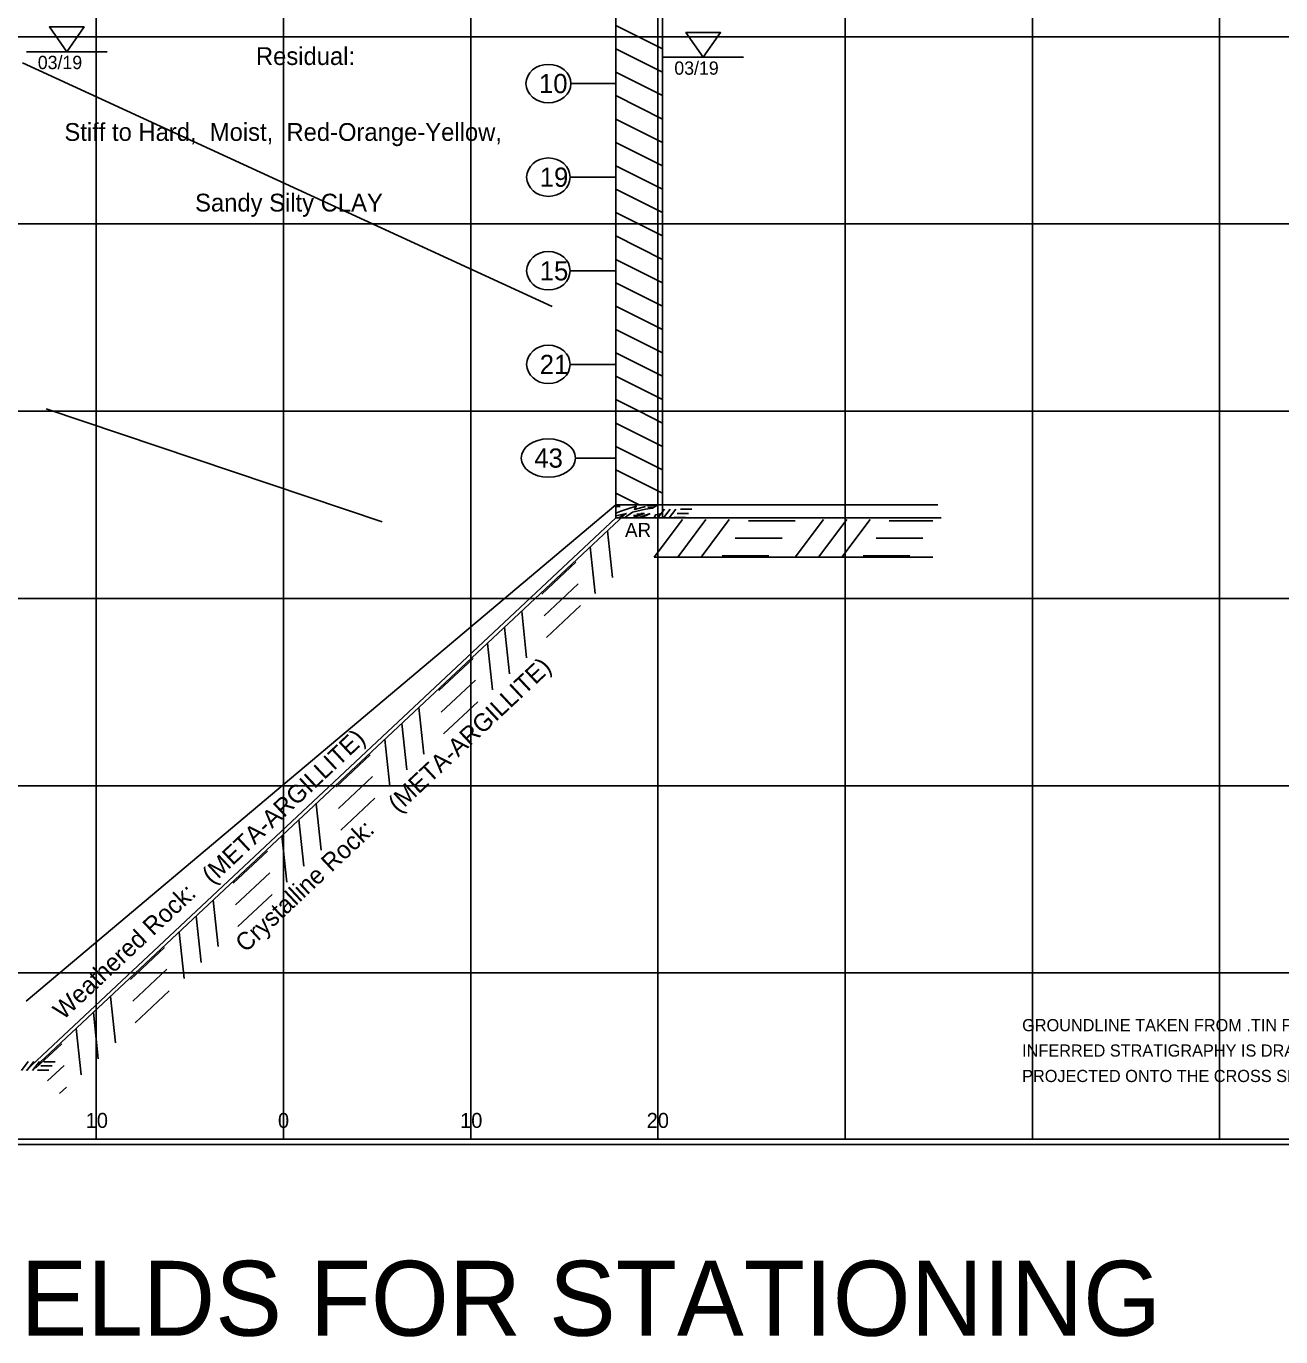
# Model space of a CAD drawing. Extents: x 278618 to 280654, y 171155 to 171855.
# Drawn here: x 280080.4 to 280147.4, y 171178.3 to 171248.3 of the extents above; entities that cross this region are included whole.
import ezdxf

# ---------------------------------------------------------------- set-up
doc = ezdxf.new("R2010")
doc.units = 0
for name, color, linetype in [('Exist Vertical Profile Ground Line', 7, 'Continuous'), ('Geotech Sheets and Borders Cell', 7, 'Continuous'), ('Prop Road Sect_ Boring - Material (Outline)', 7, 'Continuous'), ('Prop Road Sect_ Boring - Peripheral (HR Indicator)', 7, 'Continuous'), ('Prop Road Sect_ Boring - Peripheral (SPT Oval + Leader)', 7, 'Continuous'), ('Prop Road Sect_ Boring - Peripheral (SPT Tx)', 7, 'Continuous'), ('Prop Road Sect_ Material - Contact (General - Major)', 7, 'Continuous'), ('Prop Road Sect_ Material - Tx (Composite Desc)', 7, 'Continuous'), ('Prop Strc Sect_ Grid - minor', 7, 'Continuous'), ('Prop Strc Sect_ Material - Contact (General - Major)', 7, 'Continuous'), ('Scratch_Level_4', 7, 'Continuous'), ('Sheet Plot Border Inside CELL', 7, 'Continuous'), ('Water Mark (0 Hr) Cell', 7, 'Continuous'), ('Water Mark (24 Hr) Cell', 7, 'Continuous'), ('Water Mark (Dry) Cell', 7, 'Continuous')]:
    doc.layers.add(name, color=color, linetype=linetype)

msp = doc.modelspace()

# ---------------------------------------------------------------- linework, layer by layer
at = {"layer": 'Geotech Sheets and Borders Cell'}
msp.add_lwpolyline([(280024.125, 171293.859), (280174.125, 171293.859), (280174.125, 171188.859), (280024.125, 171188.859)], close=True, dxfattribs=at)
at = {"layer": 'Prop Road Sect_ Boring - Material (Outline)'}
for p, q in [((280111.875, 171248.342), (280113.123, 171247.718)), ((280111.875, 171248.342), (280113.123, 171247.718)), ((280113.123, 171247.718), (280114.372, 171247.094)), ((280113.123, 171247.718), (280114.372, 171247.094)), ((280111.875, 171247.094), (280114.372, 171245.845)), ((280111.875, 171247.094), (280114.372, 171245.845)), ((280111.875, 171247.094), (280114.372, 171245.845)), ((280111.875, 171247.094), (280114.372, 171245.845)), ((280114.372, 171247.094), (280114.375, 171247.092)), ((280114.372, 171247.094), (280114.375, 171247.092)), ((280114.372, 171247.094), (280114.375, 171247.092)), ((280114.372, 171247.094), (280114.375, 171247.092)), ((280111.875, 171245.845), (280113.123, 171245.22)), ((280111.875, 171245.845), (280113.123, 171245.22)), ((280114.372, 171245.845), (280114.375, 171245.844)), ((280114.372, 171245.845), (280114.375, 171245.844)), ((280113.123, 171245.22), (280114.372, 171244.596)), ((280113.123, 171245.22), (280114.372, 171244.596)), ((280111.875, 171244.596), (280114.372, 171243.347)), ((280111.875, 171244.596), (280114.372, 171243.347)), ((280111.875, 171244.596), (280114.372, 171243.347)), ((280111.875, 171244.596), (280114.372, 171243.347)), ((280114.372, 171244.596), (280114.375, 171244.595)), ((280114.372, 171244.596), (280114.375, 171244.595)), ((280114.372, 171244.596), (280114.375, 171244.595)), ((280114.372, 171244.596), (280114.375, 171244.595)), ((280111.875, 171243.347), (280113.123, 171242.723)), ((280111.875, 171243.347), (280113.123, 171242.723)), ((280114.372, 171243.347), (280114.375, 171243.346)), ((280114.372, 171243.347), (280114.375, 171243.346)), ((280113.123, 171242.723), (280114.372, 171242.099)), ((280113.123, 171242.723), (280114.372, 171242.099)), ((280111.875, 171242.099), (280114.372, 171240.85)), ((280111.875, 171242.099), (280114.372, 171240.85)), ((280111.875, 171242.099), (280114.372, 171240.85)), ((280111.875, 171242.099), (280114.372, 171240.85)), ((280114.372, 171242.099), (280114.375, 171242.097)), ((280114.372, 171242.099), (280114.375, 171242.097)), ((280114.372, 171242.099), (280114.375, 171242.097)), ((280114.372, 171242.099), (280114.375, 171242.097)), ((280111.875, 171240.85), (280113.123, 171240.225)), ((280111.875, 171240.85), (280113.123, 171240.225)), ((280114.372, 171240.85), (280114.375, 171240.849)), ((280114.372, 171240.85), (280114.375, 171240.849)), ((280113.123, 171240.225), (280114.372, 171239.601)), ((280113.123, 171240.225), (280114.372, 171239.601)), ((280111.875, 171239.601), (280114.372, 171238.352)), ((280111.875, 171239.601), (280114.372, 171238.352)), ((280111.875, 171239.601), (280114.372, 171238.352)), ((280111.875, 171239.601), (280114.372, 171238.352)), ((280114.372, 171239.601), (280114.375, 171239.6)), ((280114.372, 171239.601), (280114.375, 171239.6)), ((280114.372, 171239.601), (280114.375, 171239.6)), ((280114.372, 171239.601), (280114.375, 171239.6)), ((280111.875, 171238.352), (280113.123, 171237.728)), ((280111.875, 171238.352), (280113.123, 171237.728)), ((280114.372, 171238.352), (280114.375, 171238.351)), ((280114.372, 171238.352), (280114.375, 171238.351)), ((280113.123, 171237.728), (280114.372, 171237.103)), ((280113.123, 171237.728), (280114.372, 171237.103)), ((280111.875, 171237.103), (280114.372, 171235.855)), ((280111.875, 171237.103), (280114.372, 171235.855)), ((280111.875, 171237.103), (280114.372, 171235.855)), ((280111.875, 171237.103), (280114.372, 171235.855)), ((280114.372, 171237.103), (280114.375, 171237.102)), ((280114.372, 171237.103), (280114.375, 171237.102)), ((280114.372, 171237.103), (280114.375, 171237.102)), ((280114.372, 171237.103), (280114.375, 171237.102)), ((280111.875, 171235.855), (280113.123, 171235.23)), ((280111.875, 171235.855), (280113.123, 171235.23)), ((280114.372, 171235.855), (280114.375, 171235.853)), ((280114.372, 171235.855), (280114.375, 171235.853)), ((280113.123, 171235.23), (280114.372, 171234.606)), ((280113.123, 171235.23), (280114.372, 171234.606)), ((280111.875, 171234.606), (280114.372, 171233.357)), ((280111.875, 171234.606), (280114.372, 171233.357)), ((280111.875, 171234.606), (280114.372, 171233.357)), ((280111.875, 171234.606), (280114.372, 171233.357)), ((280114.372, 171234.606), (280114.375, 171234.605)), ((280114.372, 171234.606), (280114.375, 171234.605)), ((280114.372, 171234.606), (280114.375, 171234.605)), ((280114.372, 171234.606), (280114.375, 171234.605)), ((280111.875, 171233.357), (280113.123, 171232.733)), ((280111.875, 171233.357), (280113.123, 171232.733)), ((280114.372, 171233.357), (280114.375, 171233.356)), ((280114.372, 171233.357), (280114.375, 171233.356)), ((280113.123, 171232.733), (280114.372, 171232.108)), ((280113.123, 171232.733), (280114.372, 171232.108)), ((280111.875, 171232.108), (280114.372, 171230.86)), ((280111.875, 171232.108), (280114.372, 171230.86)), ((280111.875, 171232.108), (280114.372, 171230.86)), ((280111.875, 171232.108), (280114.372, 171230.86)), ((280114.372, 171232.108), (280114.375, 171232.107)), ((280114.372, 171232.108), (280114.375, 171232.107)), ((280114.372, 171232.108), (280114.375, 171232.107)), ((280114.372, 171232.108), (280114.375, 171232.107)), ((280111.875, 171230.86), (280113.123, 171230.235)), ((280111.875, 171230.86), (280113.123, 171230.235)), ((280113.123, 171230.235), (280114.372, 171229.611)), ((280113.123, 171230.235), (280114.372, 171229.611)), ((280114.372, 171230.86), (280114.375, 171230.858)), ((280114.372, 171230.86), (280114.375, 171230.858)), ((280111.875, 171229.611), (280114.372, 171228.362)), ((280111.875, 171229.611), (280114.372, 171228.362)), ((280111.875, 171229.611), (280114.372, 171228.362)), ((280111.875, 171229.611), (280114.372, 171228.362)), ((280114.372, 171229.611), (280114.375, 171229.61)), ((280114.372, 171229.611), (280114.375, 171229.61)), ((280114.372, 171229.611), (280114.375, 171229.61)), ((280114.372, 171229.611), (280114.375, 171229.61)), ((280111.875, 171228.362), (280113.123, 171227.738)), ((280111.875, 171228.362), (280113.123, 171227.738)), ((280114.372, 171228.362), (280114.375, 171228.361)), ((280114.372, 171228.362), (280114.375, 171228.361)), ((280113.123, 171227.738), (280114.372, 171227.113)), ((280113.123, 171227.738), (280114.372, 171227.113)), ((280111.875, 171227.113), (280114.372, 171225.865)), ((280111.875, 171227.113), (280114.372, 171225.865)), ((280111.875, 171227.113), (280114.372, 171225.865)), ((280111.875, 171227.113), (280114.372, 171225.865)), ((280114.372, 171227.113), (280114.375, 171227.112)), ((280114.372, 171227.113), (280114.375, 171227.112)), ((280114.372, 171227.113), (280114.375, 171227.112)), ((280114.372, 171227.113), (280114.375, 171227.112)), ((280111.875, 171225.865), (280113.123, 171225.24)), ((280111.875, 171225.865), (280113.123, 171225.24)), ((280114.372, 171225.865), (280114.375, 171225.863)), ((280114.372, 171225.865), (280114.375, 171225.863)), ((280111.875, 171224.616), (280114.372, 171223.367)), ((280111.875, 171224.616), (280114.372, 171223.367)), ((280111.875, 171224.616), (280114.372, 171223.367)), ((280111.875, 171224.616), (280114.372, 171223.367)), ((280113.123, 171225.24), (280114.372, 171224.616)), ((280113.123, 171225.24), (280114.372, 171224.616)), ((280114.372, 171224.616), (280114.375, 171224.615)), ((280114.372, 171224.616), (280114.375, 171224.615)), ((280114.372, 171224.616), (280114.375, 171224.615)), ((280114.372, 171224.616), (280114.375, 171224.615)), ((280111.875, 171223.367), (280113.123, 171222.743)), ((280111.875, 171223.367), (280113.123, 171222.743)), ((280114.372, 171223.367), (280114.375, 171223.366)), ((280114.372, 171223.367), (280114.375, 171223.366)), ((280111.913, 171222.74), (280112.138, 171222.74)), ((280111.913, 171222.74), (280112.138, 171222.74)), ((280111.913, 171222.657), (280112.113, 171222.657)), ((280111.913, 171222.657), (280112.113, 171222.657)), ((280113.538, 171222.713), (280113.938, 171222.713)), ((280113.538, 171222.713), (280113.938, 171222.713)), ((280113.588, 171222.6), (280113.863, 171222.6)), ((280113.588, 171222.6), (280113.863, 171222.6)), ((280111.875, 171222.15), (280112.443, 171222.287)), ((280111.875, 171222.15), (280112.443, 171222.287)), ((280112.443, 171222.287), (280112.013, 171222.043)), ((280112.443, 171222.287), (280112.013, 171222.043)), ((280113.414, 171222.289), (280112.774, 171222.043)), ((280113.414, 171222.289), (280112.774, 171222.043)), ((280112.813, 171222.168), (280113.099, 171222.168)), ((280112.813, 171222.168), (280113.099, 171222.168)), ((280112.997, 171222.237), (280113.277, 171222.237)), ((280112.997, 171222.237), (280113.277, 171222.237)), ((280113.709, 171222.289), (280113.069, 171222.043)), ((280113.709, 171222.289), (280113.069, 171222.043)), ((280113.214, 171222.289), (280113.414, 171222.289)), ((280113.214, 171222.289), (280113.414, 171222.289)), ((280113.709, 171222.289), (280113.232, 171222.043)), ((280113.709, 171222.289), (280113.232, 171222.043)), ((280114.372, 171222.072), (280114.259, 171222.043)), ((280114.372, 171222.072), (280114.259, 171222.043)), ((280114.372, 171222.307), (280114.375, 171222.308)), ((280114.372, 171222.307), (280114.375, 171222.308)), ((280114.372, 171222.15), (280114.375, 171222.15)), ((280114.372, 171222.15), (280114.375, 171222.15))]:
    msp.add_line(p, q, dxfattribs=at)
for points in [[(280111.875, 171250.743), (280114.375, 171250.743), (280114.375, 171222.743), (280111.875, 171222.743)], [(280111.875, 171222.743), (280114.375, 171222.743), (280114.375, 171222.043), (280111.875, 171222.043)]]:
    msp.add_lwpolyline(points, close=True, dxfattribs=at)
for points in [[(280111.875, 171222.307), (280112.142, 171222.4), (280112.521, 171222.523), (280112.967, 171222.677), (280112.912, 171222.554), (280112.87, 171222.503), (280113.467, 171222.659)], [(280111.875, 171222.307), (280112.142, 171222.4), (280112.521, 171222.523), (280112.967, 171222.677), (280112.912, 171222.554), (280112.87, 171222.503), (280113.467, 171222.659)], [(280112.334, 171222.043), (280112.763, 171222.347), (280113.463, 171222.515), (280113.838, 171222.572), (280114.125, 171222.743)], [(280112.334, 171222.043), (280112.763, 171222.347), (280113.463, 171222.515), (280113.838, 171222.572), (280114.125, 171222.743)], [(280114.372, 171222.305), (280114.313, 171222.29), (280113.988, 171222.207), (280113.923, 171222.043)], [(280114.372, 171222.305), (280114.313, 171222.29), (280113.988, 171222.207), (280113.923, 171222.043)]]:
    msp.add_lwpolyline(points, dxfattribs=at)
at = {"layer": 'Prop Road Sect_ Boring - Peripheral (HR Indicator)'}
for p, q in [((280114.125, 171222.043), (280114.486, 171222.521)), ((280114.425, 171222.043), (280114.786, 171222.521)), ((280114.725, 171222.043), (280115.086, 171222.521)), ((280114.994, 171222.059), (280115.594, 171222.059)), ((280115.162, 171222.282), (280115.762, 171222.282)), ((280115.33, 171222.505), (280115.93, 171222.505)), ((280080.125, 171192.543), (280080.486, 171193.021)), ((280080.425, 171192.543), (280080.786, 171193.021)), ((280080.725, 171192.543), (280081.086, 171193.021)), ((280080.994, 171192.559), (280081.594, 171192.559)), ((280081.162, 171192.782), (280081.762, 171192.782)), ((280081.33, 171193.005), (280081.93, 171193.005))]:
    msp.add_line(p, q, dxfattribs=at)
at = {"layer": 'Prop Road Sect_ Boring - Peripheral (SPT Oval + Leader)'}
for p, q in [((280111.875, 171245.243), (280109.475, 171245.243)), ((280111.875, 171240.243), (280109.435, 171240.243)), ((280111.875, 171235.243), (280109.435, 171235.243)), ((280111.875, 171230.243), (280109.435, 171230.243)), ((280111.875, 171225.243), (280109.725, 171225.243))]:
    msp.add_line(p, q, dxfattribs=at)
for centre, major_axis, ratio in [((280108.275, 171245.243), (1.2, 0), 0.853887), ((280108.275, 171240.243), (1.16, 0), 0.883591), ((280108.275, 171235.243), (1.16, 0), 0.883591), ((280108.275, 171230.243), (1.16, 0), 0.883591), ((280108.275, 171225.243), (1.451, 0), 0.706609)]:
    msp.add_ellipse(centre, major_axis=major_axis, ratio=ratio, dxfattribs=at)
at = {"layer": 'Prop Road Sect_ Material - Contact (General - Major)'}
for p, q in [((280081.45, 171227.873), (280099.401, 171221.842)), ((280080.375, 171196.243), (280111.875, 171222.743)), ((280114.375, 171222.743), (280129.073, 171222.743)), ((280080.375, 171192.543), (280111.875, 171222.043)), ((280080.841, 171192.706), (280112.341, 171222.206)), ((280113.934, 171219.958), (280115.438, 171221.952)), ((280114.375, 171222.043), (280129.252, 171222.043)), ((280115.184, 171219.958), (280116.688, 171221.952)), ((280116.434, 171219.958), (280117.938, 171221.952)), ((280121.458, 171219.958), (280122.962, 171221.952)), ((280122.708, 171219.958), (280124.212, 171221.952)), ((280123.958, 171219.958), (280125.462, 171221.952)), ((280111.428, 171221.352), (280111.693, 171218.869)), ((280110.516, 171220.497), (280110.781, 171218.014)), ((280113.934, 171219.958), (280128.811, 171219.958)), ((280106.849, 171217.063), (280107.114, 171214.58)), ((280105.937, 171216.209), (280106.202, 171213.726)), ((280105.024, 171215.354), (280105.289, 171212.871)), ((280101.357, 171211.92), (280101.623, 171209.437)), ((280100.445, 171211.066), (280100.71, 171208.583)), ((280099.533, 171210.211), (280099.798, 171207.728)), ((280095.866, 171206.777), (280096.131, 171204.294)), ((280094.953, 171205.923), (280095.219, 171203.44)), ((280094.041, 171205.068), (280094.306, 171202.585)), ((280090.374, 171201.634), (280090.639, 171199.151)), ((280089.462, 171200.78), (280089.727, 171198.297)), ((280088.549, 171199.926), (280088.815, 171197.442)), ((280084.883, 171196.492), (280085.148, 171194.008)), ((280083.97, 171195.637), (280084.236, 171193.154)), ((280083.058, 171194.783), (280083.323, 171192.3))]:
    msp.add_line(p, q, dxfattribs=at)
for points in [[(280118.957, 171221.883), (280121.457, 171221.883)], [(280126.481, 171221.883), (280128.811, 171221.883)], [(280118.257, 171220.955), (280120.757, 171220.955)], [(280125.781, 171220.955), (280128.281, 171220.955)], [(280117.557, 171220.027), (280120.057, 171220.027)], [(280125.081, 171220.027), (280127.581, 171220.027)], [(280109.743, 171219.68), (280107.919, 171217.971)], [(280109.867, 171218.524), (280108.042, 171216.815)], [(280109.99, 171217.368), (280108.166, 171215.659)], [(280104.252, 171214.537), (280102.427, 171212.828)], [(280104.375, 171213.381), (280102.551, 171211.672)], [(280104.499, 171212.225), (280102.674, 171210.516)], [(280098.76, 171209.394), (280096.935, 171207.685)], [(280098.884, 171208.238), (280097.059, 171206.529)], [(280099.007, 171207.082), (280097.182, 171205.373)], [(280093.269, 171204.251), (280091.444, 171202.542)], [(280093.392, 171203.095), (280091.567, 171201.386)], [(280093.516, 171201.939), (280091.691, 171200.23)], [(280087.777, 171199.108), (280085.952, 171197.399)], [(280087.901, 171197.952), (280086.076, 171196.243)], [(280088.024, 171196.796), (280086.199, 171195.087)], [(280082.285, 171193.965), (280080.888, 171192.656)], [(280082.409, 171192.809), (280081.522, 171191.978)], [(280082.532, 171191.653), (280082.156, 171191.301)]]:
    msp.add_lwpolyline(points, dxfattribs=at)
at = {"layer": 'Prop Strc Sect_ Grid - minor'}
for p, q in [((280084.125, 171188.859), (280084.125, 171293.859)), ((280094.125, 171188.859), (280094.125, 171293.859)), ((280104.125, 171188.859), (280104.125, 171293.859)), ((280114.125, 171188.859), (280114.125, 171293.859)), ((280124.125, 171188.859), (280124.125, 171285.961)), ((280134.125, 171188.859), (280134.125, 171285.961)), ((280144.125, 171188.859), (280144.125, 171285.961)), ((280174.125, 171247.743), (280024.125, 171247.743)), ((280174.125, 171237.743), (280024.125, 171237.743)), ((280174.125, 171227.743), (280024.125, 171227.743)), ((280174.125, 171217.743), (280024.125, 171217.743)), ((280174.125, 171207.743), (280024.125, 171207.743)), ((280174.125, 171197.743), (280024.125, 171197.743))]:
    msp.add_line(p, q, dxfattribs=at)
at = {"layer": 'Prop Strc Sect_ Material - Contact (General - Major)'}
msp.add_line((280080.178, 171246.344), (280108.478, 171233.344), dxfattribs=at)
at = {"layer": 'Sheet Plot Border Inside CELL'}
msp.add_lwpolyline([(280008.608, 171188.575), (280175.375, 171188.575), (280175.375, 171294.142), (280008.608, 171294.142)], close=True, dxfattribs=at)
at = {"layer": 'Water Mark (0 Hr) Cell'}
for p, q in [((280080.393, 171246.943), (280082.55, 171246.943)), ((280082.55, 171246.943), (280084.706, 171246.943)), ((280114.393, 171246.643), (280116.55, 171246.643)), ((280116.55, 171246.643), (280118.706, 171246.643))]:
    msp.add_line(p, q, dxfattribs=at)
for points in [[(280082.55, 171246.943), (280081.622, 171248.269), (280083.477, 171248.269)], [(280116.55, 171246.643), (280115.622, 171247.969), (280117.477, 171247.969)]]:
    msp.add_lwpolyline(points, close=True, dxfattribs=at)

# ---------------------------------------------------------------- texts
at = {"layer": 'Exist Vertical Profile Ground Line'}
for s, p in [('GROUNDLINE TAKEN FROM .TIN FILE RECIEVED BY NCDOT DATED 03/28/2019.', (280133.58, 171194.632)), ('INFERRED STRATIGRAPHY IS DRAWN THROUGH THE BORINGS WITH BOTH ', (280133.58, 171193.275)), ('PROJECTED ONTO THE CROSS SECTION', (280133.58, 171191.918))]:
    msp.add_text(s, height=0.65, dxfattribs=at).set_placement(p)
at = {"layer": 'Geotech Sheets and Borders Cell'}
for s, p in [('10', (280083.561, 171189.469)), ('0', (280093.83, 171189.469)), ('10', (280103.561, 171189.469)), ('20', (280113.525, 171189.469))]:
    msp.add_text(s, height=0.8, dxfattribs=at).set_placement(p)
at = {"layer": 'Prop Road Sect_ Boring - Peripheral (SPT Tx)'}
for s, p in [('10', (280107.774, 171244.73)), ('19', (280107.815, 171239.73)), ('15', (280107.815, 171234.73)), ('21', (280107.815, 171229.73)), ('43', (280107.524, 171224.73))]:
    msp.add_text(s, height=1.025, dxfattribs=at).set_placement(p)
at = {"layer": 'Prop Road Sect_ Material - Tx (Composite Desc)'}
for s, p in [('Residual:', (280092.655, 171246.234)), ('Stiff to Hard,  Moist,  Red-Orange-Yellow,', (280082.425, 171242.181)), ('Sandy Silty CLAY', (280089.405, 171238.409))]:
    msp.add_text(s, height=0.95, dxfattribs=at).set_placement(p)
for s, p in [('(META-ARGILLITE)', (280100.261, 171206.256)), ('(META-ARGILLITE)', (280090.324, 171202.436)), ('Crystalline Rock:', (280092.1, 171198.794)), ('Weathered Rock:', (280082.363, 171195.198))]:
    msp.add_text(s, height=0.95, rotation=43.12212, dxfattribs=at).set_placement(p)
at = {"layer": 'Scratch_Level_4'}
msp.add_text('EDIT DATA FIELDS FOR STATIONING', height=4.00002, dxfattribs=at).set_placement((280045.896, 171178.37))
at = {"layer": 'Water Mark (24 Hr) Cell'}
for p in [(280081.002, 171246.015), (280115.002, 171245.715)]:
    msp.add_text('03/19', height=0.7087, dxfattribs=at).set_placement(p)
at = {"layer": 'Water Mark (Dry) Cell'}
msp.add_text('AR', height=0.75, dxfattribs=at).set_placement((280112.369, 171221.026))

doc.saveas('drawing.dxf')
